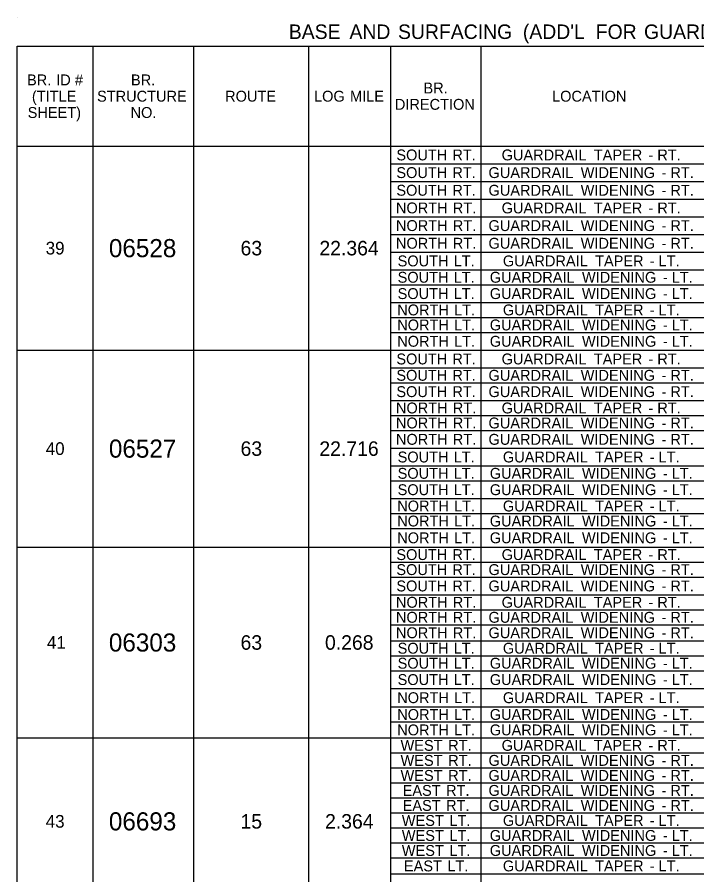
# Model space of a CAD drawing. Extents: x 544250 to 1930787, y -1948365 to 596640.
# Drawn here: x 544964.8 to 545339.7, y -1947838.8 to -1947365.4 of the extents above; entities that cross this region are included whole.
import ezdxf

# ---------------------------------------------------------------- set-up
doc = ezdxf.new("R2010")
doc.units = 0
doc.layers.add('Default', color=7, linetype='Continuous')

msp = doc.modelspace()

# ---------------------------------------------------------------- linework, layer by layer
at = {"layer": 'Default'}
for p, q in [((544964.76, -1947365.4), (544964.76, -1947365.4)), ((544964.76, -1947381.48), (545647.75, -1947381.48)), ((544964.76, -1948209.26), (544964.76, -1947381.48)), ((545006.69, -1948198.53), (545006.69, -1947381.48)), ((545062.26, -1948198.53), (545062.26, -1947381.48)), ((545125.64, -1948198.53), (545125.64, -1947381.48)), ((545170.98, -1948198.53), (545170.98, -1947381.48)), ((545220.7, -1948198.53), (545220.7, -1947381.48)), ((544964.76, -1947436.57), (545647.75, -1947436.57)), ((545170.98, -1947446.32), (545647.75, -1947446.32)), ((545170.98, -1947456.07), (545647.75, -1947456.07)), ((545170.98, -1947465.82), (545647.75, -1947465.82)), ((545170.98, -1947475.57), (545647.75, -1947475.57)), ((545170.98, -1947485.32), (545647.75, -1947485.32)), ((545170.98, -1947495.07), (545647.75, -1947495.07)), ((545170.98, -1947504.82), (545647.75, -1947504.82)), ((545170.98, -1947513.11), (545647.75, -1947513.11)), ((545170.98, -1947522.86), (545647.75, -1947522.86)), ((545170.98, -1947531.15), (545647.75, -1947531.15)), ((545170.98, -1947539.43), (545647.75, -1947539.43)), ((544964.76, -1947549.18), (545647.75, -1947549.18)), ((545170.98, -1947558.93), (545647.75, -1947558.93)), ((545170.98, -1947567.22), (545647.75, -1947567.22)), ((545170.98, -1947576.97), (545647.75, -1947576.97)), ((545170.98, -1947585.26), (545647.75, -1947585.26)), ((545170.98, -1947593.55), (545647.75, -1947593.55)), ((545170.98, -1947603.3), (545647.75, -1947603.3)), ((545170.98, -1947613.05), (545647.75, -1947613.05)), ((545170.98, -1947621.33), (545647.75, -1947621.33)), ((545170.98, -1947631.08), (545647.75, -1947631.08)), ((545170.98, -1947639.37), (545647.75, -1947639.37)), ((545170.98, -1947647.66), (545647.75, -1947647.66)), ((544964.76, -1947657.9), (545647.75, -1947657.9)), ((545170.98, -1947666.18), (545647.75, -1947666.18)), ((545170.98, -1947674.47), (545647.75, -1947674.47)), ((545170.98, -1947684.22), (545647.75, -1947684.22)), ((545170.98, -1947692.51), (545647.75, -1947692.51)), ((545170.98, -1947700.8), (545647.75, -1947700.8)), ((545170.98, -1947709.57), (545647.75, -1947709.57)), ((545170.98, -1947717.86), (545647.75, -1947717.86)), ((545170.98, -1947726.15), (545647.75, -1947726.15)), ((545170.98, -1947735.9), (545647.75, -1947735.9)), ((545170.98, -1947746.13), (545647.75, -1947746.13)), ((545170.98, -1947754.42), (545647.75, -1947754.42)), ((544964.76, -1947763.2), (545647.75, -1947763.2)), ((545170.98, -1947771.48), (545647.75, -1947771.48)), ((545170.98, -1947779.77), (545647.75, -1947779.77)), ((545170.98, -1947788.06), (545647.75, -1947788.06)), ((545170.98, -1947796.35), (545647.75, -1947796.35)), ((545170.98, -1947804.63), (545647.75, -1947804.63)), ((545170.98, -1947812.92), (545647.75, -1947812.92)), ((545170.98, -1947821.21), (545647.75, -1947821.21)), ((545170.98, -1947829.5), (545647.75, -1947829.5)), ((545170.98, -1947838.27), (545647.75, -1947838.27))]:
    msp.add_line(p, q, dxfattribs=at)

# ---------------------------------------------------------------- texts
for s, height, p in [('BASE', 8, (545114.61, -1947377.44)), (' AND', 8, (545145.11, -1947377.44)), (' SURFACING', 8, (545171.88, -1947377.44)), (" (ADD'L", 8, (545240.76, -1947377.44)), (' FOR', 8, (545280.95, -1947377.44)), (' GUARDRAIL)', 8, (545307.6, -1947377.44)), ('BR.', 6, (544970.2, -1947403.03)), (' ID', 6, (544984.06, -1947403.03)), (' #', 6, (544994.36, -1947403.03)), ('BR.', 6, (545027.54, -1947403.03)), ('(TITLE', 6, (544972.9, -1947412.03)), ('STRUCTURE', 6, (545008.83, -1947412.03)), ('ROUTE', 6, (545079.49, -1947412.03)), ('LOG', 6, (545128.51, -1947412.03)), (' MILE', 6, (545146.17, -1947412.03)), ('BR.', 6, (545188.91, -1947407.53)), ('LOCATION', 6, (545259.84, -1947412.03)), ('DIRECTION', 6, (545173.12, -1947416.53)), ('SHEET)', 6, (544970.57, -1947421.03)), ('NO.', 6, (545027.31, -1947421.03)), ('SOUTH', 6, (545173.95, -1947444.45)), (' RT.', 6, (545202.62, -1947444.45)), ('GUARDRAIL', 6, (545232.02, -1947444.45)), (' TAPER', 6, (545280.64, -1947444.45)), (' RT.', 6, (545315.67, -1947444.45)), (' -', 6, (545310.81, -1947444.45)), ('SOUTH', 6, (545173.95, -1947454.2)), (' RT.', 6, (545202.62, -1947454.2)), ('GUARDRAIL', 6, (545224.78, -1947454.2)), (' WIDENING', 6, (545273.4, -1947454.2)), (' RT.', 6, (545322.9, -1947454.2)), (' -', 6, (545318.05, -1947454.2)), ('SOUTH', 6, (545173.95, -1947463.95)), (' RT.', 6, (545202.62, -1947463.95)), ('GUARDRAIL', 6, (545224.78, -1947463.95)), (' WIDENING', 6, (545273.4, -1947463.95)), (' RT.', 6, (545322.9, -1947463.95)), (' -', 6, (545318.05, -1947463.95)), ('NORTH', 6, (545173.72, -1947473.7)), ('GUARDRAIL', 6, (545232.02, -1947473.7)), (' RT.', 6, (545202.85, -1947473.7)), (' TAPER', 6, (545280.64, -1947473.7)), (' -', 6, (545310.81, -1947473.7)), (' RT.', 6, (545315.67, -1947473.7)), ('NORTH', 6, (545173.72, -1947483.45)), (' RT.', 6, (545202.85, -1947483.45)), ('GUARDRAIL', 6, (545224.78, -1947483.45)), (' WIDENING', 6, (545273.4, -1947483.45)), (' -', 6, (545318.05, -1947483.45)), (' RT.', 6, (545322.9, -1947483.45)), ('39', 7, (544980.5, -1947496.38)), ('06528', 10, (545015.37, -1947497.88)), ('63', 8, (545087.99, -1947496.88)), ('22.364', 8, (545131.49, -1947496.88)), ('NORTH', 6, (545173.72, -1947493.2)), (' RT.', 6, (545202.85, -1947493.2)), ('GUARDRAIL', 6, (545224.78, -1947493.2)), (' WIDENING', 6, (545273.4, -1947493.2)), (' -', 6, (545318.05, -1947493.2)), (' RT.', 6, (545322.9, -1947493.2)), ('SOUTH', 6, (545174.65, -1947502.95)), (' LT.', 6, (545203.32, -1947502.95)), ('GUARDRAIL', 6, (545232.72, -1947502.95)), (' TAPER', 6, (545281.34, -1947502.95)), (' -', 6, (545311.51, -1947502.95)), (' LT.', 6, (545316.36, -1947502.95)), ('SOUTH', 6, (545174.65, -1947511.97)), (' LT.', 6, (545203.32, -1947511.97)), ('GUARDRAIL', 6, (545225.48, -1947511.97)), (' WIDENING', 6, (545274.1, -1947511.97)), (' -', 6, (545318.75, -1947511.97)), (' LT.', 6, (545323.6, -1947511.97)), ('SOUTH', 6, (545174.65, -1947520.98)), ('GUARDRAIL', 6, (545225.48, -1947520.98)), (' WIDENING', 6, (545274.1, -1947520.98)), (' LT.', 6, (545203.32, -1947520.98)), (' -', 6, (545318.75, -1947520.98)), (' LT.', 6, (545323.6, -1947520.98)), ('NORTH', 6, (545174.42, -1947530)), (' LT.', 6, (545203.55, -1947530)), ('GUARDRAIL', 6, (545232.72, -1947530)), (' TAPER', 6, (545281.34, -1947530)), (' LT.', 6, (545316.36, -1947530)), (' -', 6, (545311.51, -1947530)), ('NORTH', 6, (545174.42, -1947538.29)), (' LT.', 6, (545203.55, -1947538.29)), ('GUARDRAIL', 6, (545225.48, -1947538.29)), (' WIDENING', 6, (545274.1, -1947538.29)), (' LT.', 6, (545323.6, -1947538.29)), (' -', 6, (545318.75, -1947538.29)), ('NORTH', 6, (545174.42, -1947547.31)), (' LT.', 6, (545203.55, -1947547.31)), ('GUARDRAIL', 6, (545225.48, -1947547.31)), (' WIDENING', 6, (545274.1, -1947547.31)), (' LT.', 6, (545323.6, -1947547.31)), (' -', 6, (545318.75, -1947547.31)), ('SOUTH', 6, (545173.95, -1947557.06)), (' RT.', 6, (545202.62, -1947557.06)), ('GUARDRAIL', 6, (545232.02, -1947557.06)), (' TAPER', 6, (545280.64, -1947557.06)), (' RT.', 6, (545315.67, -1947557.06)), (' -', 6, (545310.81, -1947557.06)), ('SOUTH', 6, (545173.95, -1947566.08)), (' RT.', 6, (545202.62, -1947566.08)), ('GUARDRAIL', 6, (545224.78, -1947566.08)), (' WIDENING', 6, (545273.4, -1947566.08)), (' RT.', 6, (545322.9, -1947566.08)), (' -', 6, (545318.05, -1947566.08)), ('SOUTH', 6, (545173.95, -1947575.1)), (' RT.', 6, (545202.62, -1947575.1)), ('GUARDRAIL', 6, (545224.78, -1947575.1)), (' WIDENING', 6, (545273.4, -1947575.1)), (' RT.', 6, (545322.9, -1947575.1)), (' -', 6, (545318.05, -1947575.1)), ('NORTH', 6, (545173.72, -1947584.12)), (' RT.', 6, (545202.85, -1947584.12)), ('GUARDRAIL', 6, (545232.02, -1947584.12)), (' TAPER', 6, (545280.64, -1947584.12)), (' RT.', 6, (545315.67, -1947584.12)), (' -', 6, (545310.81, -1947584.12)), ('NORTH', 6, (545173.72, -1947592.4)), (' RT.', 6, (545202.85, -1947592.4)), ('GUARDRAIL', 6, (545224.78, -1947592.4)), (' WIDENING', 6, (545273.4, -1947592.4)), (' -', 6, (545318.05, -1947592.4)), (' RT.', 6, (545322.9, -1947592.4)), ('NORTH', 6, (545173.72, -1947601.42)), (' RT.', 6, (545202.85, -1947601.42)), ('GUARDRAIL', 6, (545224.78, -1947601.42)), (' WIDENING', 6, (545273.4, -1947601.42)), (' RT.', 6, (545322.9, -1947601.42)), ('40', 7, (544980.52, -1947607.04)), ('06527', 10, (545015.37, -1947608.54)), ('63', 8, (545087.99, -1947607.54)), ('22.716', 8, (545131.47, -1947607.54)), (' -', 6, (545318.05, -1947601.42)), ('SOUTH', 6, (545174.65, -1947611.17)), (' LT.', 6, (545203.32, -1947611.17)), ('GUARDRAIL', 6, (545232.72, -1947611.17)), (' TAPER', 6, (545281.34, -1947611.17)), (' -', 6, (545311.51, -1947611.17)), (' LT.', 6, (545316.36, -1947611.17)), ('SOUTH', 6, (545174.65, -1947620.19)), (' LT.', 6, (545203.32, -1947620.19)), ('GUARDRAIL', 6, (545225.48, -1947620.19)), (' WIDENING', 6, (545274.1, -1947620.19)), (' LT.', 6, (545323.6, -1947620.19)), (' -', 6, (545318.75, -1947620.19)), ('SOUTH', 6, (545174.65, -1947629.21)), (' LT.', 6, (545203.32, -1947629.21)), ('GUARDRAIL', 6, (545225.48, -1947629.21)), (' WIDENING', 6, (545274.1, -1947629.21)), (' LT.', 6, (545323.6, -1947629.21)), (' -', 6, (545318.75, -1947629.21)), ('NORTH', 6, (545174.42, -1947638.23)), (' LT.', 6, (545203.55, -1947638.23)), ('GUARDRAIL', 6, (545232.72, -1947638.23)), (' TAPER', 6, (545281.34, -1947638.23)), (' LT.', 6, (545316.36, -1947638.23)), (' -', 6, (545311.51, -1947638.23)), ('NORTH', 6, (545174.42, -1947646.52)), (' LT.', 6, (545203.55, -1947646.52)), ('GUARDRAIL', 6, (545225.48, -1947646.52)), (' WIDENING', 6, (545274.1, -1947646.52)), (' LT.', 6, (545323.6, -1947646.52)), (' -', 6, (545318.75, -1947646.52)), ('NORTH', 6, (545174.42, -1947655.78)), (' LT.', 6, (545203.55, -1947655.78)), ('GUARDRAIL', 6, (545225.48, -1947655.78)), (' WIDENING', 6, (545274.1, -1947655.78)), (' LT.', 6, (545323.6, -1947655.78)), (' -', 6, (545318.75, -1947655.78)), ('SOUTH', 6, (545173.95, -1947665.04)), (' RT.', 6, (545202.62, -1947665.04)), ('GUARDRAIL', 6, (545232.02, -1947665.04)), (' TAPER', 6, (545280.64, -1947665.04)), (' RT.', 6, (545315.67, -1947665.04)), (' -', 6, (545310.81, -1947665.04)), ('SOUTH', 6, (545173.95, -1947673.33)), (' RT.', 6, (545202.62, -1947673.33)), ('GUARDRAIL', 6, (545224.78, -1947673.33)), (' WIDENING', 6, (545273.4, -1947673.33)), (' -', 6, (545318.05, -1947673.33)), (' RT.', 6, (545322.9, -1947673.33)), ('SOUTH', 6, (545173.95, -1947682.35)), (' RT.', 6, (545202.62, -1947682.35)), ('GUARDRAIL', 6, (545224.78, -1947682.35)), (' WIDENING', 6, (545273.4, -1947682.35)), (' -', 6, (545318.05, -1947682.35)), (' RT.', 6, (545322.9, -1947682.35)), ('NORTH', 6, (545173.72, -1947691.37)), (' RT.', 6, (545202.85, -1947691.37)), ('GUARDRAIL', 6, (545232.02, -1947691.37)), (' TAPER', 6, (545280.64, -1947691.37)), (' RT.', 6, (545315.67, -1947691.37)), (' -', 6, (545310.81, -1947691.37)), ('NORTH', 6, (545173.72, -1947699.65)), (' RT.', 6, (545202.85, -1947699.65)), ('GUARDRAIL', 6, (545224.78, -1947699.65)), (' WIDENING', 6, (545273.4, -1947699.65)), (' RT.', 6, (545322.9, -1947699.65)), (' -', 6, (545318.05, -1947699.65)), ('NORTH', 6, (545173.72, -1947708.18)), (' RT.', 6, (545202.85, -1947708.18)), ('GUARDRAIL', 6, (545224.78, -1947708.18)), (' WIDENING', 6, (545273.4, -1947708.18)), (' RT.', 6, (545322.9, -1947708.18)), ('41', 7, (544981.19, -1947714.05)), ('06303', 10, (545015.36, -1947715.55)), ('63', 8, (545087.99, -1947714.55)), ('0.268', 8, (545134.57, -1947714.55)), (' -', 6, (545318.05, -1947708.18)), ('SOUTH', 6, (545174.65, -1947716.72)), (' LT.', 6, (545203.32, -1947716.72)), ('GUARDRAIL', 6, (545232.72, -1947716.72)), (' TAPER', 6, (545281.34, -1947716.72)), (' LT.', 6, (545316.36, -1947716.72)), (' -', 6, (545311.51, -1947716.72)), ('SOUTH', 6, (545174.65, -1947725)), (' LT.', 6, (545203.32, -1947725)), ('GUARDRAIL', 6, (545225.48, -1947725)), (' WIDENING', 6, (545274.1, -1947725)), (' -', 6, (545318.75, -1947725)), (' LT.', 6, (545323.6, -1947725)), ('SOUTH', 6, (545174.65, -1947734.02)), ('GUARDRAIL', 6, (545225.48, -1947734.02)), (' WIDENING', 6, (545274.1, -1947734.02)), (' LT.', 6, (545203.32, -1947734.02)), (' -', 6, (545318.75, -1947734.02)), (' LT.', 6, (545323.6, -1947734.02)), ('NORTH', 6, (545174.42, -1947744.02)), (' LT.', 6, (545203.55, -1947744.02)), ('GUARDRAIL', 6, (545232.72, -1947744.02)), (' TAPER', 6, (545281.34, -1947744.02)), (' -', 6, (545311.51, -1947744.02)), (' LT.', 6, (545316.36, -1947744.02)), ('NORTH', 6, (545174.42, -1947753.28)), (' LT.', 6, (545203.55, -1947753.28)), ('GUARDRAIL', 6, (545225.48, -1947753.28)), (' WIDENING', 6, (545274.1, -1947753.28)), (' -', 6, (545318.75, -1947753.28)), (' LT.', 6, (545323.6, -1947753.28)), ('NORTH', 6, (545174.42, -1947761.81)), (' LT.', 6, (545203.55, -1947761.81)), ('GUARDRAIL', 6, (545225.48, -1947761.81)), (' WIDENING', 6, (545274.1, -1947761.81)), (' LT.', 6, (545323.6, -1947761.81)), (' -', 6, (545318.75, -1947761.81)), ('WEST', 6, (545176.26, -1947770.34)), (' RT.', 6, (545200.31, -1947770.34)), ('GUARDRAIL', 6, (545232.02, -1947770.34)), (' TAPER', 6, (545280.64, -1947770.34)), (' RT.', 6, (545315.67, -1947770.34)), (' -', 6, (545310.81, -1947770.34)), ('WEST', 6, (545176.26, -1947778.63)), (' RT.', 6, (545200.31, -1947778.63)), ('GUARDRAIL', 6, (545224.78, -1947778.63)), (' WIDENING', 6, (545273.4, -1947778.63)), (' RT.', 6, (545322.9, -1947778.63)), (' -', 6, (545318.05, -1947778.63)), ('WEST', 6, (545176.26, -1947786.92)), (' RT.', 6, (545200.31, -1947786.92)), ('GUARDRAIL', 6, (545224.78, -1947786.92)), (' WIDENING', 6, (545273.4, -1947786.92)), (' -', 6, (545318.05, -1947786.92)), (' RT.', 6, (545322.9, -1947786.92)), ('EAST', 6, (545177.42, -1947795.2)), (' RT.', 6, (545199.15, -1947795.2)), ('GUARDRAIL', 6, (545224.78, -1947795.2)), (' WIDENING', 6, (545273.4, -1947795.2)), (' RT.', 6, (545322.9, -1947795.2)), (' -', 6, (545318.05, -1947795.2)), ('EAST', 6, (545177.42, -1947803.49)), (' RT.', 6, (545199.15, -1947803.49)), ('GUARDRAIL', 6, (545224.78, -1947803.49)), (' WIDENING', 6, (545273.4, -1947803.49)), (' RT.', 6, (545322.9, -1947803.49)), (' -', 6, (545318.05, -1947803.49)), ('43', 7, (544980.51, -1947812.77)), ('06693', 10, (545015.36, -1947814.27)), ('15', 8, (545087.96, -1947813.27)), ('2.364', 8, (545134.6, -1947813.27)), ('WEST', 6, (545176.96, -1947811.78)), (' LT.', 6, (545201.01, -1947811.78)), ('GUARDRAIL', 6, (545232.72, -1947811.78)), (' TAPER', 6, (545281.34, -1947811.78)), (' LT.', 6, (545316.36, -1947811.78)), (' -', 6, (545311.51, -1947811.78)), ('WEST', 6, (545176.96, -1947820.07)), (' LT.', 6, (545201.01, -1947820.07)), ('GUARDRAIL', 6, (545225.48, -1947820.07)), (' WIDENING', 6, (545274.1, -1947820.07)), (' -', 6, (545318.75, -1947820.07)), (' LT.', 6, (545323.6, -1947820.07)), ('WEST', 6, (545176.96, -1947828.35)), (' LT.', 6, (545201.01, -1947828.35)), ('GUARDRAIL', 6, (545225.48, -1947828.35)), (' WIDENING', 6, (545274.1, -1947828.35)), (' LT.', 6, (545323.6, -1947828.35)), (' -', 6, (545318.75, -1947828.35)), ('EAST', 6, (545178.12, -1947836.88)), (' LT.', 6, (545199.85, -1947836.88)), ('GUARDRAIL', 6, (545232.72, -1947836.88)), (' TAPER', 6, (545281.34, -1947836.88)), (' LT.', 6, (545316.36, -1947836.88)), (' -', 6, (545311.51, -1947836.88))]:
    msp.add_text(s, height=height, dxfattribs=at).set_placement(p)

doc.saveas('drawing.dxf')
